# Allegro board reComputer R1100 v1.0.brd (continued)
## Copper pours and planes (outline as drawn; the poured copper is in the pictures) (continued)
GND_ISO on LYR2_GND, LYR3, LYR4_GND, LYR5_PWR, LYR7_GND: 57.61,22.16 58.17,22.16 58.83,21.5 60.81,21.5 62.33,19.98 62.33,17.77 65.38,14.72 71.88,14.72 73.1,15.94 104.65,15.94 105.72,14.87 105.72,3.59 105.06,2.93 70.69,2.93 69.52,4.1 69.52,9.56 68.71,10.38 67.74,10.38 67.46,10.65 67.46,12.48 66.89,13.06 62.55,13.06 62.31,13.3 62.31,14.24 57.43,19.11 57.43,21.98
GND_ISO on LYR6: 69.88,14.72 71.88,14.72 73.1,15.94 104.65,15.94 105.72,14.87 105.72,3.59 105.06,2.93 70.69,2.93 69.52,4.1 69.52,14.36
VCC_USB1 on TOP: 98.24,53.49 97.94,53.78 97.94,54.65 98.05,54.75 98.48,54.75 98.76,55.03 98.76,55.18 100.59,57.01 102.03,57.01 102.31,56.73 102.31,56.35 101.48,55.51 101.48,55.03 99.94,53.49
VCC_USB1 on TOP: 110.75,73.72 110.75,73.93 109.45,75.22 109.45,75.68 109.3,75.83 108.1,75.83 107.88,75.6 107.88,74.74 109.12,73.49 110.52,73.49
VCC_USB1 on LYR3: 100,53.68 98.22,53.68 98.05,53.86 98.05,56.58 106.71,65.24 106.71,75.3 107.11,75.7 109.45,75.7 109.88,75.27 109.88,59.35 108.66,58.13 104.45,58.13
VCC_USB2 on TOP: 105.97,51.24 105.54,51.24 105.08,51.7 104.02,51.7 103.56,51.24 102.34,51.24 101.96,51.62 101.27,51.62 101.12,51.78 101.12,52.69 101.2,52.77 104.09,52.77 104.32,52.54 105.97,52.54 106.2,52.31 106.2,51.47
VCC_USB2 on TOP: 109.6,70.24 110.77,70.24 111.58,71.06 113.52,71.06 113.74,70.83 113.74,69.94 113.44,69.63 109.71,69.63 109.55,69.79 109.55,70.19
VCC_USB2 on LYR3: 101.27,52.82 105.97,52.82 106.99,53.83 106.99,55.87 112.6,61.48 112.6,69.07 111.74,69.94 111.74,70.47 111.91,70.65 114.1,70.65 114.35,70.4 114.35,60.06 109.4,55.1 109.4,52.06 108.56,51.22 101.37,51.22 101.12,51.47 101.12,52.67
VDD33_HUB1 on TOP: 43.21,33.79 42.65,33.79 42.34,34.1 42.34,36.59 42.7,36.94 44.66,36.94 44.91,36.69 44.91,35.98 44.76,35.83 43.46,35.83 43.31,35.67 43.31,35.09 43.49,34.91 43.49,34.07
VDD33_HUB1 on TOP: 59.16,27.42 59.16,28.89 58.98,29.07 58.37,29.07 58.22,28.92 58.22,27.34 58.45,27.11 58.85,27.11
VDD33_HUB1 on LYR6: 56.67,38.42 45.27,38.42 42.29,35.44 42.29,30.59 43.18,29.7 57.13,29.7 58.27,28.56 59.01,28.56 59.29,28.84 59.29,32.27 58.6,32.96 45.47,32.96 45.16,33.26 45.16,33.62 46.92,35.37 56.62,35.37 57,35.75 57,38.09
VDD33_HUB2 on TOP: 101.12,73.7 101.4,73.7 101.88,74.18 102.52,74.18 102.75,73.95 102.75,72.94 102.54,72.73 101.27,72.73 100.99,73.01 100.99,73.57
VDD33_HUB2 on LYR3: 94.49,65.26 100.43,65.26 102.67,67.5 102.67,73.24 102.34,73.57 98.45,73.57 97.36,74.66 96.07,74.66 91.93,70.52 87.81,70.52 86.62,71.72 86.62,74.46 86.16,74.92 77.07,74.92 76.66,74.51 76.66,73.14 76.96,72.83 81.38,72.83 86.87,67.35 92.41,67.35
VDD33A_HUB1 on TOP: 57.28,26.07 57.53,26.33 57.53,28.82 57.25,29.09 56.75,29.09 55.63,27.98 54.41,27.98 54.28,27.85 54.28,27.6 54.41,27.47 54.76,27.47 55.55,26.68 55.55,26.2 55.68,26.07
VDD33A_HUB1 on LYR3: 57.36,28.46 56.59,28.46 55.55,29.5 55.55,33.03 55.83,33.31 57.28,33.31 57.53,33.06 57.53,28.64
VDD33A_HUB1 on LYR6: 46.13,25.46 45.32,25.46 45.16,25.62 45.16,26.66 47.2,28.69 52.56,28.69 52.91,28.33 55.83,28.33 56.44,28.94 57.48,28.94 57.74,28.69 57.74,26.53 56.21,25.01 51.26,25.01 51.11,25.16 51.11,25.54 50.88,25.77 46.43,25.77
VDD_3V3_PCIE on TOP: 20.42,68.77 20.47,68.82 20.47,69.94 20.37,70.04 19.36,70.04 19.23,69.91 19.23,68.87 19.33,68.77
VDD_3V3_PCIE on BOTTOM: 21.39,65.54 19.26,65.54 19.15,65.65 19.15,69.84 19.38,70.07 21.52,70.07 21.59,69.99 21.59,65.75
VDD_3V3_PCIE on BOTTOM: 19.2,47.48 19.2,48.53 21.74,51.07 21.74,52.62 21.54,52.82 16.92,52.82 16.28,52.18 16.28,50 15.06,48.78 15.06,47.64 15.39,47.31 19.03,47.31
VDD_3V3_PCIE on LYR3: 18.77,48.68 16.49,48.68 15.65,49.52 15.65,68.54 17.15,70.04 20.42,70.04 20.6,69.86 20.6,50.51
VDD_3V3_SYS on TOP: 102.19,75.78 101.96,75.55 101.96,75.07 102.11,74.92 102.67,74.92 103.15,74.43 104.02,74.43 104.22,74.64 104.22,75.55 103.99,75.78
VDD_3V3_SYS on TOP: 43.89,30.75 43.89,32.8 43.64,33.06 42.47,33.06 42.19,32.78 42.19,30.72 42.42,30.49 43.64,30.49
VDD_3V3_SYS on TOP: 73.38,26.08 75.46,26.08 75.69,25.85 75.69,25.14 75.49,24.94 73.43,24.94 73.23,25.14 73.23,25.93
VDD_3V3_SYS on TOP: 15.05,5.35 15.05,6.31 15.2,6.46 16.39,6.46 16.51,6.34 16.51,5.3 16.31,5.09 15.31,5.09
VDD_3V3_SYS on TOP: 63.81,26.94 63.81,27.57 64.01,27.77 64.67,27.77 64.85,27.6 64.85,26.89 64.7,26.73 64.01,26.73
VDD_3V3_SYS on TOP: 27.59,70.95 23.42,70.95 23.17,70.7 23.17,70.12 23.35,69.94 25.89,69.94 25.99,70.04 25.99,70.22 26.16,70.4 26.8,70.4 27.16,70.75 27.59,70.75 27.66,70.83 27.66,70.88
VDD_3V3_SYS on BOTTOM: 75.69,24.07 75.69,25.72 75.62,25.79 74.88,25.79 74.81,25.72 74.81,24.04 74.86,23.99 75.62,23.99
VDD_3V3_SYS on BOTTOM: 17.12,18.5 15.37,18.5 15.22,18.66 15.22,18.81 16.41,20 16.41,20.41 16.56,20.56 17.38,20.56 17.58,20.36 17.58,18.96
VDD_3V3_SYS on BOTTOM: 13.95,48.58 10.19,48.58 9.76,48.14 9.76,45.1 9.78,45.07 10.52,45.07 11.15,45.71 13.92,45.71 14.18,45.96 14.18,48.35
VDD_3V3_SYS on BOTTOM: 56.44,44.12 54.71,44.12 54.41,44.43 54.41,49.02 55.37,49.99 62.21,49.99 62.61,49.58 62.61,47.14 62.23,46.76 57.53,46.76 56.77,46 56.77,44.45
VDD_3V3_SYS on BOTTOM: 41.76,27.85 41.76,29.12 41.43,29.45 40.39,29.45 40.03,29.09 40.03,27.9 40.26,27.67 41.58,27.67
VDD_3V3_SYS on LYR5_PWR: outline of 88 points within 2.29,4.96 110.19,80.89
VDD_5V_SYS on TOP: 99.98,52.84 100.74,52.84 100.84,52.74 100.84,51.95 100.69,51.8 100.05,51.8 99.88,51.98 99.88,52.74
VDD_5V_SYS on TOP: 110.67,72.76 109.35,72.76 108.99,73.11 108.38,73.11 108.16,72.88 108.16,72.12 108.44,71.84 108.99,71.84 109.35,72.2 110.67,72.2 110.77,72.3 110.77,72.66
VDD_5V_SYS on TOP: 78.92,21.6 78.92,23.63 78.84,23.71 78.34,23.71 77.98,24.07 77.98,24.7 77.83,24.85 76.66,24.85 76.56,24.75 76.56,22.9 76.66,22.8 77.4,22.8 77.96,22.24 77.96,21.73 78.18,21.5 78.82,21.5
VDD_5V_SYS on TOP: 56.44,75.46 56.44,76.14 56.16,76.42 52.38,76.42 51.79,77 51.79,78.96 52.17,79.34 53.75,79.34 54.51,78.57 56.75,78.57 57.99,77.33 58.63,77.33 58.73,77.23 58.73,75.51 58.63,75.41 58.45,75.41 58.45,76.12 58.42,76.15 58.37,76.15 58.35,76.12 58.35,75.41 58.04,75.41 58.04,76.12 58.02,76.15 57.97,76.15 57.94,76.12 57.94,75.41 57.66,75.41 57.66,76.12 57.64,76.15 57.58,76.15 57.56,76.12 57.56,75.41 57.25,75.41 57.25,76.12 57.23,76.15 57.18,76.15 57.15,76.12 57.15,75.41 56.85,75.41 56.85,76.12 56.82,76.15 56.77,76.15 56.75,76.12 56.75,75.41 56.49,75.41
VDD_5V_SYS on BOTTOM: 100.74,52.84 99.67,52.84 99.21,52.39 98.07,52.39 93.39,57.07 82.06,57.07 81.94,56.96 81.94,54.14 82.04,54.04 93.02,54.04 97.16,49.9 100.41,49.9 100.89,50.38 100.89,52.69
VDD_5V_SYS on BOTTOM: 76.28,43.88 74.96,43.88 74.55,44.28 74.55,48.3 75.92,49.67 81.59,49.67 82.22,49.03 82.22,47.61 81.97,47.36 81.38,47.36 80.67,46.65 77.09,46.65 76.76,46.32 76.76,44.36
VDD_5V_SYS on BOTTOM: 107.39,72.66 107.39,75.07 107.65,75.32 108.69,75.32 108.87,75.15 108.87,73.52 109.32,73.06 109.32,72.73 110.19,71.87 110.19,71.31 110.04,71.16 108.89,71.16
VDD_5V_SYS on BOTTOM: 5.41,37.45 5.08,37.78 5.08,38.8 5.39,39.1 9.02,39.1 10.44,37.68 10.44,36.26 9.98,35.8 9.73,35.8 9.6,35.93 9.6,36.64 8.79,37.45
VDD_5V_SYS on LYR3: 6.43,38.21 6.43,41.92 15.04,50.53 15.04,68.9 18.7,72.55 18.7,73.32 18.37,73.65 15.7,73.65 10.87,68.82 10.87,50.41 4.37,43.9 4.37,38.21 4.73,37.86 6.07,37.86
VDD_5V_SYS on LYR3: 80.39,47.84 80.39,67.45 80.83,67.88 83.54,67.88 83.95,67.47 83.95,47.81 83.64,47.51 80.72,47.51
VDD_5V_SYS on LYR5_PWR: 80.98,49.54 77.8,49.54 77.24,48.98 77.24,38.75 76.48,37.98 76.48,23.86 76.76,23.58 78.26,23.58 78.67,23.99 78.67,31.08 81.41,33.82 81.41,49.11
VDD_5V_SYS on LYR5_PWR: 82.6,66.59 78.11,66.59 77.68,67.02 77.68,68.13 76.23,69.58 43.94,69.58 42.06,67.7 37.21,67.7 33.68,71.23 17.88,71.23 16.82,72.3 16.82,75.35 19.87,78.4 65.03,78.4 68.84,74.59 70.44,74.59 70.45,74.57 79.75,74.57 82.98,71.34 82.98,66.97
VDD_5V_SYS on LYR5_PWR: 81.69,57.97 82.22,58.51 98.43,58.51 99.93,60.01 99.93,68.13 101.09,69.3 102.8,69.3 103.41,69.91 103.41,71.84 104.83,73.27 108.97,73.27 109.53,72.71 109.53,66.46 110.54,65.44 114.45,65.44 117.25,62.65 117.25,59.5 115.8,58.05 105.49,58.05 103.63,56.2 84.43,56.2 83.82,55.59 81.97,55.59 81.69,55.87
VDD_IN on TOP: 67.54,30.59 67.24,30.59 67.06,30.42 67.06,26.96 67.59,26.43 71.25,26.43 71.81,26.99 71.81,30.09 71.27,30.62 69.78,30.62 69.6,30.44 69.6,28.23 69.55,28.18 69.09,28.18 69.04,28.23 69.04,30.47 68.89,30.62 68.48,30.62 68.33,30.47 68.33,28.28 68.25,28.21 67.87,28.21 67.77,28.31 67.77,30.36
VDD_IN on BOTTOM: 17.33,80.05 18.52,80.05 18.85,80.38 18.85,81.34 18.57,81.62 17.27,81.62 17.07,81.42 17.07,80.3
VDD_IN on BOTTOM: 74.83,40.22 76.25,40.22 76.43,40.4 85.83,40.4 86.24,39.99 86.24,38.11 85.63,37.5 80.06,37.5 79.86,37.71 79.86,38.14 79.56,38.44 77.29,38.44 76.1,39.64 74.81,39.64 74.68,39.76 74.68,40.07
VDD_IN on BOTTOM: 64.8,53.33 42.37,53.33 42.24,53.45 42.24,53.89 43.39,55.03 64.8,55.03 65.05,54.77 65.05,53.58
VDD_IN on BOTTOM: 54.28,40.25 55.7,40.25 56.09,40.63 57.1,40.63 57.3,40.83 62.38,40.83 62.69,40.52 62.69,39.33 62.51,39.15 59.16,39.15 58.93,38.92 58.93,38.42 58.8,38.29 58.65,38.29 58.45,38.49 58.45,38.9 58.19,39.15 55.91,39.15 55.4,39.66 54.23,39.66 54.13,39.76 54.13,40.09
VDD_IN on LYR3: 64.65,39.18 61.62,39.18 61.42,39.38 61.42,42.91 62.28,43.78 62.28,53.61 62.49,53.81 64.65,53.81 64.82,53.63 64.82,53.05 65.18,52.69 65.18,39.71
VDD_IN on LYR3: 31.96,79.21 34.93,79.21 39.19,74.94 39.19,71.72 43.21,67.7 43.21,53.58 42.93,53.3 40.85,53.3 40.49,53.66 40.49,65.14 34.88,70.75 34.88,71.59 31.52,74.94 31.52,78.78
VDD_IN on LYR6: 83.44,36.16 79.07,36.16 78.34,35.42 78.34,29.3 77.65,28.61 60.76,28.61 59.21,30.16 59.21,40.27 59.69,40.75 63.91,40.75 64.42,40.25 64.42,37.65 64.72,37.35 65.56,37.35 66.07,37.86 70.8,37.86 72.5,39.56 83.31,39.56 83.85,39.03 83.85,36.56
VDD_IN on LYR6: 32.21,79.11 21.14,79.11 18.87,81.37 17.22,81.37 16.97,81.11 16.97,79.16 19.76,76.36 32.31,76.36 32.59,76.64 32.59,78.73
VDD_LTE_3V3 on TOP: 106.53,31.99 106.53,33.82 106.76,34.05 108,34.05 108.26,33.79 108.26,31.97 108.1,31.81 106.71,31.81
VDD_LTE_3V3 on TOP: 77.93,30.97 77.93,29.91 76.94,28.92 76,28.92 75.44,28.36 75.44,27.04 75.16,26.76 73.51,26.76 73.26,27.01 73.26,29.09 74.15,29.98 74.73,29.98 75.82,31.08 75.82,31.97 79.4,35.55 79.4,36.03 79.53,36.16 80.85,36.16 81.1,35.9 81.1,34.15
VDD_LTE_3V3 on BOTTOM: 75.19,73.7 75.19,75.91 75.08,76.01 74.15,76.01 74.04,75.91 74.04,73.85 74.27,73.62 75.11,73.62
VDD_LTE_3V3 on BOTTOM: 107.34,33.08 104.27,33.08 103.1,34.25 103.1,35.98 103.33,36.21 103.84,36.21 104.7,35.34 108.18,35.34 108.31,35.22 108.31,34.73 108.21,34.63 107.75,34.63 107.5,34.38 107.5,33.24
VDD_LTE_3V3 on BOTTOM: 80.11,36.13 79.61,36.13 79.02,35.55 79.02,33.92 79.23,33.72 80.06,33.72 80.29,33.95 80.29,35.95
VDD_LTE_3V3 on LYR3: 78.72,33.72 78.36,34.07 78.36,44.51 75.49,47.38 75.49,64.68 74.09,66.08 74.09,75.78 74.27,75.96 75.97,75.96 76.1,75.83 76.1,69.71 79,66.81 79,48.75 81.18,46.57 81.18,34.96 79.94,33.72
VDD_LTE_3V3 on LYR6: 79.58,25.62 87.48,25.62 88.98,27.11 107.7,27.11 108.49,27.9 108.49,34.76 107.55,35.7 79.4,35.7 78.97,35.27 78.97,26.22
VDD_UPS on TOP: 67.08,32.37 67.08,35.32 67.74,35.98 71.55,35.98 73.46,37.88 75.52,37.88 78.35,40.72 78.35,43.43 78.74,43.83 83.09,43.83 83.49,43.42 83.49,40.45 79.48,36.44 78.67,36.44 75.16,32.93 73.79,32.93 73.05,32.19 69.78,32.19 69.6,32.37 69.6,34.51 69.55,34.56 69.12,34.56 69.04,34.48 69.04,32.35 68.89,32.19 68.43,32.19 68.33,32.3 68.33,34.53 68.28,34.58 67.87,34.58 67.77,34.48 67.77,32.35 67.62,32.19 67.26,32.19
VDD_UPS on BOTTOM: 82.65,41.46 82.43,41.69 82.43,44.13 83.04,44.74 83.9,44.74 84.03,44.87 84.03,48.14 84.48,48.6 87.53,48.6 87.94,48.2 87.94,42.89 86.51,41.46
DO_VDD on BOTTOM: 93.4,25.62 91.75,25.62 91.59,25.46 91.59,23.96 91.67,23.89 92.71,23.89 93.27,23.33 93.27,22.62 93.4,22.49 95.51,22.49 95.66,22.64 95.66,23.35
EXT_VCC_9_36V on TOP: 94.03,36.92 94.03,41.49 94.62,42.07 97.16,42.07 97.67,41.57 97.67,36.99 97.06,36.38 94.57,36.38
EXT_VCC_9_36V on BOTTOM: 97.41,40.55 95.48,40.55 91.7,44.33 91.7,45.15 91.26,45.58 88.98,45.58 88.85,45.71 88.85,46.11 88.95,46.21 89.56,46.21 89.61,46.27 89.61,46.8 89.56,46.85 88.9,46.85 88.83,46.93 88.83,47.36 88.95,47.48 89.56,47.48 89.64,47.56 89.64,48.04 89.56,48.12 89,48.12 88.83,48.3 88.83,48.78 89.03,48.98 91.98,48.98 92.38,48.58 92.38,47.23 92.71,46.9 94.24,46.9 97.67,43.47 97.67,40.8
HDMI0_5V on TOP: 98.38,47.46 98.38,51.17 98.2,51.35 97.18,51.35 97.03,51.19 97.03,47.48 97.28,47.23 98.15,47.23
HDMI0_5V on LYR3: 101.27,41.21 98.3,41.21 95.56,43.95 95.56,48.09 95.96,48.5 97.69,48.5 97.89,48.3 97.89,47.43 97.34,46.87 97.34,44.67 98.22,43.78 101.42,43.78 101.7,43.5 101.7,41.64
LORA_3V3 on BOTTOM: 42.98,26.91 40.59,26.91 40.39,26.71 40.39,25.95 40.64,25.69 43,25.69 43.23,25.92 43.23,26.66
LORA_3V3 on BOTTOM: 53.52,23.79 53.52,27.8 53.32,28 53.11,28 52.99,27.88 52.99,26.1 52.94,26.05 52.76,26.05 52.71,26.1 52.71,27.85 52.58,27.98 52.35,27.98 52.17,27.8 52.17,26.1 50.55,24.47 50.55,23.68 50.78,23.46 53.19,23.46
LORA_3V3 on BOTTOM: 71.02,34.12 71.02,36.66 71.17,36.82 71.63,36.82 72.16,36.28 72.16,32.93 71.53,32.3 59.26,32.3 58.98,32.57 58.98,36.05 59.13,36.21 59.34,36.21 59.51,36.03 59.51,34.07 59.82,33.77 70.67,33.77
LORA_3V3 on LYR5_PWR: 51.31,23.35 42.04,23.35 41.48,23.91 41.48,26.94 44.02,29.48 44.02,35.39 44.25,35.62 59.64,35.62 59.97,35.29 59.97,33.62 51.69,25.34 51.69,23.74
POE_12V on TOP: 35.84,44.87 31.35,44.87 27.66,41.19 27.66,39.79 28.32,39.13 34.83,39.13 36.3,40.6 36.3,44.41
POE_12V on BOTTOM: 44.05,50.74 40.36,47.05 40.36,44.41 38.03,42.07 34.32,42.07 33.58,42.81 33.58,45.68 34.27,46.37 36.78,46.37 37.06,46.65 37.06,48.45 41.63,53.02 92.84,53.02 95.1,50.76 95.1,47.74 94.62,47.26 93.04,47.26 92.69,47.61 92.69,49.57 91.52,50.74
POE_IN_N on TOP: 23.07,16.22 19.99,16.22 19.74,16.47 19.74,17.74 20.27,18.27 21.82,18.27 23.07,19.52 23.07,21.91 23.4,22.24 25.86,22.24 26.16,21.93 26.16,19.19 25.33,18.35 25.2,18.35
POE_IN_N on TOP: 11.61,9.64 12.6,9.64 12.96,9.28 14.46,9.28 14.73,9 14.73,7.78 14.28,7.33 11.51,7.33 11.23,7.61 11.23,9.26
POE_IN_N on TOP: 30.74,17.18 30.74,15.12 31.32,14.54 33.78,14.54 34.19,14.95 34.19,17.28 33.71,17.77 31.32,17.77
POE_IN_N on BOTTOM: 26.67,18.33 25.45,18.33 25.15,18.63 25.15,19.77 25.35,19.98 26.7,19.98 26.9,19.77 26.9,18.55
POE_IN_N on LYR3: 33.66,14.57 33.25,14.57 31.35,16.47 26.37,16.47 25,17.84 25,19.72 25.25,19.98 27.03,19.98 28.17,18.83 33.51,18.83 33.99,18.35 33.99,14.9
POE_IN_N on LYR6: 21.11,17.94 19.54,17.94 19.23,17.64 19.23,16.17 18.98,15.91 15.29,15.91 12,12.62 12,8.58 12.42,8.17 14.73,8.17 15.09,8.52 15.09,10.38 18.18,13.46 19.52,13.46 21.36,15.3 21.36,17.69
POE_IN_N1 on TOP: 40.01,15.33 36.15,15.33 34.85,16.62 34.85,23.05 33.76,24.14 28.43,24.14 27.94,24.62 27.94,25.67 28.3,26.02 36.25,26.02 37.32,24.95 37.32,20.31 40.44,17.18 40.44,15.76
POE_IN_P on TOP: 20.98,15.07 21.57,15.66 23.37,15.66 24.77,17.06 25.81,17.06 26.06,16.8 26.06,14.44 25.3,13.68 18.37,13.68 14.35,9.66 13.16,9.66 12.58,10.25 10.42,10.25 9.98,9.82 9.98,8.88 9.5,8.39 9.1,8.39 8.82,8.67 8.82,11.77 10.39,13.35 15.85,13.35 17.05,14.54 17.91,14.54 18.44,15.07
POE_IN_P1 on TOP: 38.08,21.78 38.08,25.64 37.06,26.66 27.43,26.66 26.44,27.65 13.41,27.65 12.22,26.45 12.22,24.78 11.66,24.22 8.18,24.22 7.62,24.78 7.62,25.82 10.92,29.12 37.72,29.12 41.63,25.21 41.63,21.86 41.15,21.37 38.48,21.37
UART_3V3 on TOP: 60.63,5.57 60.63,7.1 60.4,7.33 58.45,7.33 58.24,7.12 58.24,6.31 58.37,6.18 58.73,6.18 59.57,5.35 60.4,5.35
USBA_GND on TOP: 105.41,65.21 114.23,65.21 114.71,65.7 115.27,65.7 115.55,65.42 115.55,64.15 115.27,63.87 105.39,63.87 105.13,64.12 105.13,64.93
USBA_GND on BOTTOM: 115.32,65.77 114.81,65.77 114.1,65.06 114.1,63.87 114.48,63.49 115.17,63.49 115.55,63.87 115.55,65.54
N21080778 on TOP: 112.99,51.29 116.26,51.29 116.26,46.04 115.06,44.84 108.12,44.84 107.6,45.09 107.35,45.61 107.35,45.77 107.63,46.32 108.2,46.54 112.17,46.54 112.99,47.37
N21080778 on TOP, BOTTOM, LYR2_GND, LYR7_GND: 113.35,39.11 113.07,38.56 112.5,38.34 101.72,38.34 101.2,38.59 100.95,39.11 100.95,39.27 101.23,39.82 101.8,40.04 112.58,40.04 113.1,39.8 113.35,39.28
N21080778 on LYR3, LYR6: 114.55,46.54 116.46,44.63 116.46,40.26 114.54,38.34 101.72,38.34 101.2,38.59 100.95,39.11 100.95,39.27 101.23,39.82 101.8,40.04 113.73,40.04 114.68,40.99 114.68,43.89 113.73,44.84 109.02,44.84 109.02,46.54
N21080778 on LYR4_GND, LYR5_PWR: 114.55,46.54 116.46,44.63 116.46,40.26 114.54,38.34 101.72,38.34 101.2,38.59 100.95,39.11 100.95,39.27 101.23,39.82 101.8,40.04 113.73,40.04 114.68,40.99 114.68,43.89 113.73,44.84 98.62,44.84 98.1,45.09 97.85,45.61 97.85,45.77 98.13,46.32 98.7,46.54
N21116206 on TOP: 103.91,28.23 99.09,28.23 98.86,28.46 98.86,31.84 98.99,31.97 102.87,31.97 103.18,31.66 103.18,30.92 104.07,30.03 104.07,28.38
N21116206 on BOTTOM: 112.68,22.11 112.68,13.17 109.92,10.41 109.92,6.55 109.58,6.21 106.23,6.21 106.02,6.41 106.02,13.58 107.5,15.05 107.5,25.13 107.83,25.46 108.97,25.46 109.2,25.23 109.2,13.42 107.75,11.98 107.75,8.06 107.88,7.94 108.33,7.94 108.4,8 108.4,11.7 109.96,13.26 109.96,21.98 110.14,22.16 112.63,22.16
N21116206 on LYR3: 108.94,23.53 108.94,27.49 106.15,30.29 103.18,30.29 102.8,29.91 102.8,27.24 106.63,23.41 108.82,23.41
N21116390 on TOP: 92.23,32.02 92,32.24 92,33.11 92.2,33.31 96.78,33.31 96.88,33.41 96.88,35.62 96.67,35.83 89.44,35.83 89.18,35.57 89.18,28.76 89.74,28.21 96.62,28.21 96.78,28.36 96.78,31.71 96.47,32.02
N21392725 on BOTTOM: 4.42,36.05 9.22,36.05 9.35,35.93 9.35,34.2 9.12,33.97 7.8,33.97 6.96,34.81 4.45,34.81 4.24,35.01 4.24,35.88
N21629438 on TOP: 96.75,43.8 96.75,46.77 96.4,47.13 94.9,47.13 94.64,46.87 94.64,43.88 94.92,43.6 96.55,43.6
N22027038 on TOP: 22.58,23.38 21.92,23.38 21.72,23.58 21.72,25.34 23.78,27.39 24.11,27.39 24.34,27.16 24.34,26.4 22.79,24.85 22.79,23.58
N22027038 on TOP: 20.42,19.75 20.42,18.71 20.58,18.55 21.47,18.55 21.92,19.01 21.92,19.75 21.74,19.93 20.6,19.93
N22027038 on BOTTOM: 22.13,22.24 21.54,22.24 21.36,22.41 21.36,23.71 21.64,23.99 22.48,23.99 22.66,23.81 22.66,23.48 22.3,23.13 22.3,22.41
N22027038 on LYR3: 21.82,18.76 21.11,18.76 20.88,18.99 20.88,21.86 21.67,22.64 21.67,23.74 21.85,23.91 22.74,23.91 22.96,23.68 22.96,22.39 22.13,21.55 22.13,19.06
N22027110 on TOP: 8.87,18.38 9.91,18.38 10.06,18.53 10.06,19.72 9.91,19.87 8.87,19.87 8.69,19.7 8.69,18.55
N22027110 on TOP: 17.71,22.34 17.05,22.34 16.84,22.54 16.84,26.45 17.86,27.47 18.34,27.47 18.47,27.34 18.47,26.48 17.96,25.97 17.96,22.59
N22027110 on LYR6: 9.53,19.19 8.92,19.19 8.69,19.42 8.69,20.84 11.58,23.74 12.4,23.74 12.91,24.24 17.66,24.24 17.96,23.94 17.96,22.72 17.55,22.31 12.65,22.31
N22027117 on TOP: 20.96,22.31 20.3,22.31 20.09,22.52 20.09,26.63 20.91,27.44 21.29,27.44 21.41,27.32 21.41,26.45 21.21,26.25 21.21,22.57
N22027117 on TOP: 16.72,19.75 16.72,18.71 16.87,18.55 18.06,18.55 18.21,18.71 18.21,19.75 18.04,19.93 16.89,19.93
N22027117 on LYR3: 21.01,23.66 18.95,23.66 18.49,23.2 18.49,22.44 17.43,21.37 17.43,18.99 17.66,18.76 18.72,18.76 18.95,18.99 18.95,21.27 20.3,22.62 20.91,22.62 21.14,22.85 21.14,23.53
N22028382 on TOP: 14.46,22.19 13.79,22.19 13.59,22.39 13.59,26.07 14.84,27.32 15.09,27.32 15.22,27.19 15.22,26.33 14.71,25.82 14.71,22.44
N22028382 on TOP: 11.28,18.33 12.32,18.33 12.47,18.48 12.47,19.67 12.32,19.82 11.28,19.82 11.1,19.65 11.1,18.5
N22028382 on BOTTOM: 11.2,19.37 12.27,19.37 12.44,19.53 12.42,19.54 12.42,20.66 14.81,23.05 14.81,23.43 14.53,23.71 13.03,23.71 11.1,21.78 11.1,19.47
N22028488 on TOP: 19.36,19.87 18.67,19.87 18.47,19.67 18.47,18.58 14.89,15 13.9,15 13.67,14.77 13.67,13.98 13.87,13.78 15.75,13.78 19.26,17.28 19.26,17.87 19.61,18.22 19.61,19.62
N22028491 on TOP: 15.67,19.93 14.99,19.93 14.66,19.6 14.66,18.17 13.77,17.28 13.77,16.73 14.15,16.34 15.52,16.34 15.95,16.78 15.95,19.65
N22029929 on TOP: 29.64,14.9 27.99,14.9 27.64,15.25 27.64,22.82 28.25,23.43 32.62,23.43 33.17,22.87 33.17,20.61 32.67,20.1 31.02,20.1 30.25,19.34 30.25,15.51
N22029929 on BOTTOM: 28.83,18.58 28.83,19.9 28.55,20.18 27.84,20.18 27.64,19.98 27.64,18.55 27.87,18.33 28.58,18.33
N22038032 on TOP: 14.48,21.73 13.59,21.73 12.96,22.36 12.04,22.36 11.74,22.06 11.74,20.71 12.14,20.31 14.51,20.31 14.68,20.48 14.68,21.53
N22038032 on TOP: 20.91,21.73 20.02,21.73 19.79,21.5 19.79,20.99 20.02,20.76 20.88,20.76 21.11,20.99 21.11,21.53
N22038032 on TOP: 17.71,21.73 16.82,21.73 16.59,21.5 16.59,20.99 16.82,20.76 17.68,20.76 17.91,20.99 17.91,21.53
N22038032 on BOTTOM: 21.97,21.86 20.09,21.86 19.81,21.58 19.81,20.97 20.02,20.76 22.08,20.76 22.23,20.92 22.23,21.6
N22038032 on LYR6: 20.27,20.76 15.12,20.76 14.58,20.23 13.08,20.23 12.83,20.48 12.83,21.68 13.13,21.98 20.22,21.98 20.42,21.78 20.42,20.92
N23452929 on TOP: 108.05,51.37 107.19,51.37 106.94,51.62 106.94,52.46 107.5,53.02 107.5,57.85 107.7,58.05 108.56,58.05 108.84,57.77 108.84,52.16
N23613464 on BOTTOM: 70.51,40.88 67.46,40.88 67.11,41.24 67.11,42.71 68.33,43.93 68.33,47.18 67.97,47.54 66.98,47.54 66.8,47.71 66.8,48.48 67.11,48.78 69.9,48.78 70.79,47.89 70.79,41.16
N23616337 on BOTTOM: 50.17,40.95 49.13,40.95 48.8,41.28 48.8,43.03 48.01,43.82 46.76,43.82 46.31,44.27 46.31,48.49 46.71,48.9 49.84,48.9 50.6,48.13 50.6,41.38
N23763799 on TOP: 113.49,32.93 115.09,34.53 115.09,36.94 115.62,37.48 117.53,37.48 118.04,36.97 118.04,33.92 116.79,32.68 116.79,31.56 116.82,31.53 116.82,18.96 110.29,12.43 110.29,1.59 110.21,1.51 108.94,1.51 108.56,1.89 108.56,5.55 109.12,6.11 109.12,8.37 107.88,9.61 106.86,9.61 106.63,9.84 106.63,13.04 113.49,19.9
N23869571 on TOP: 99.04,51.95 97.16,51.95 96.9,52.21 96.9,52.79 97.11,53 99.06,53 99.21,52.84 99.21,52.13
N23955153 on TOP: 18.42,3.69 18.42,4.56 18.21,4.76 17.4,4.76 16.97,5.19 16.97,6.26 17.07,6.36 17.71,6.36 18.9,5.17 18.9,3.59 18.82,3.52 18.6,3.52
N23982561 on TOP: 74.2,17.16 74.2,18.81 74.63,19.24 74.63,21.98 74.5,22.11 73.13,22.11 73.03,22.01 73.03,17.36 73.33,17.06 74.09,17.06
N234528750 on TOP: 105.97,56.83 104.4,56.83 103.61,57.62 101.48,57.62 101.3,57.8 101.3,58.74 101.5,58.94 104.17,58.94 104.93,58.18 105.92,58.18 106.17,57.92 106.17,57.03

Small or netless copper shapes (teardrops, artwork), in the pictures only: 2 on TOP

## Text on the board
Ref Des/Assembly Bottom: Assembly_Bottom
Ref Des/Silkscreen Bottom: CSI | TPM | 2A | 1A | 2B | 1B | ISO_G | DI1 | DO1 | DO2 | DI2 | DO_G | DI_G | RX1 | RX2 | TX2 | TX1 | M.2_KEY_M | V1.0 | reComputer R1100 | Nano SIM | DC:9-36V | PCIe2 | Mini | PCIe1 | 2280
Ref Des/Assembly Top: Assembly_Top
Ref Des/Silkscreen Top: BOOT | NOR | UPS | PE | DISPLAY | USBA | LED | POE | ETH0/1G/POE | ETH1/100M | USBC | RST | Micro SD | RTC
PAGE_OUTLINE: W:5/S:7 | W:4/S:8
User.45: FIGURE | FINISHED_SIZE | 8.0 | 15.75 | 21.65 | 31.5 | 35.43 | 36.0 | 40.0 | 43.31 | 47.24 | 55.12 | 57.09 | 59.06 | 63.0 | 90.55 | 122.05 | 146.85 | 165.35 | 169.29 | 41.34 | 62.99 | 66.93 | 127.95 | 128.0 | 29.53x21.65 | 43.31x19.69 | 70.87x19.69 | 106.3x35.43 | ROTATION | - | 90.000 | 0.000 | DRILL CHART: TOP to BOTTOM | ALL UNITS ARE IN MILS | SLOT HOLES: TOP to BOTTOM | TOLERANCE_DRILL | +0.0/-0.0 | +3.0/-3.0 | +5.0/-5.0 | PLATED | NON-PLATED | QTY | 1737 | 4 | 14 | 19 | 2 | 6 | 8 | 1 | 7 | 12 | 18 | 3 | 1891 | TOTAL HOLES:
